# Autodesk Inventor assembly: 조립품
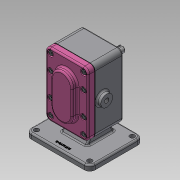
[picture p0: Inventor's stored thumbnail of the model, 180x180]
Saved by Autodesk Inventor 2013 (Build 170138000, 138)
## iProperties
Created: 2020-04
Part Number: 조립품
Document SubType Name: Assembly
Designer: default
Author: default
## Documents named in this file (11)
- C:\Users\default.default-PC\Desktop\700407V1055\조립품.iam
- C:\Users\default.default-PC\Desktop\700407V1055\본체.ipt
- C:\Users\default.default-PC\Desktop\700407V1055\개스킷.ipt
- C:\Users\default.default-PC\Desktop\700407V1055\메인축.ipt
- C:\Users\default.default-PC\Desktop\700407V1055\베어링부시.ipt
- C:\Users\default.default-PC\Desktop\700407V1055\볼트 M5.ipt
- C:\Users\default.default-PC\Desktop\700407V1055\서브축.ipt
- C:\Users\default.default-PC\Desktop\700407V1055\스퍼기어.ipt
- C:\Users\default.default-PC\Desktop\700407V1055\오일 실 16 28 7.ipt
- C:\Users\default.default-PC\Desktop\700407V1055\커버.ipt
- C:\Users\default.default-PC\Desktop\700407V1055\키 6 x 6 x 18.ipt
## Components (1 placed, 1 different names)
1. 개스킷:1
